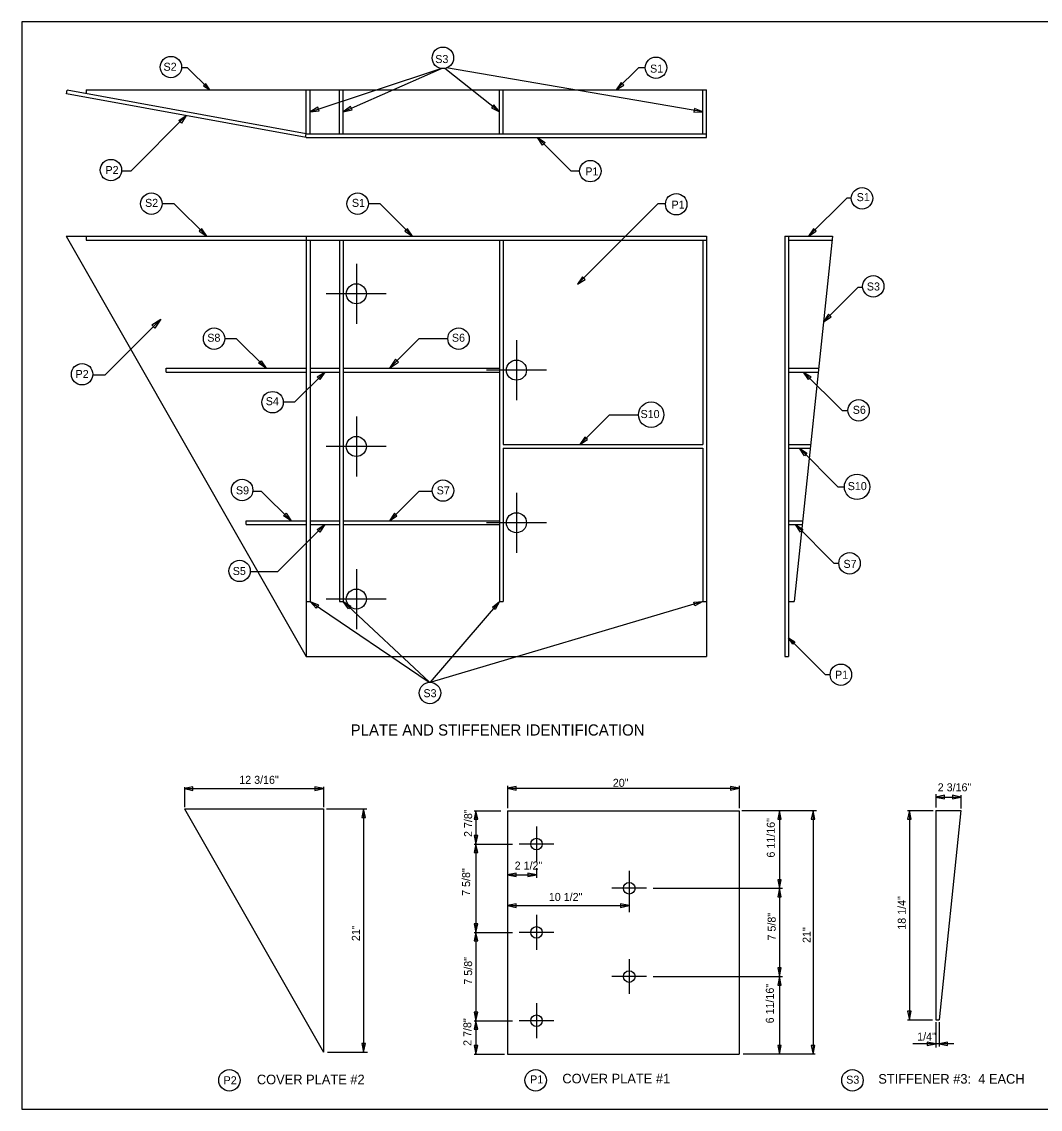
# Model space of a CAD drawing. Extents: x -439.1 to -407.9, y -458.1 to -437.7.
# Drawn here: x -439.11 to -420.02, y -458.05 to -437.68 of the extents above; entities that cross this region are included whole.
import ezdxf

# ---------------------------------------------------------------- set-up
doc = ezdxf.new("R2010")
doc.units = 0
for name, color, linetype in [('Common-Notes', 7, 'Continuous'), ('Draft_Named_Boundary', 7, 'Continuous'), ('Level 4', 7, 'Continuous'), ('Level 45', 7, 'Continuous')]:
    doc.layers.add(name, color=color, linetype=linetype)

msp = doc.modelspace()

# ---------------------------------------------------------------- linework, layer by layer
at = {"layer": 'Draft_Named_Boundary'}
msp.add_lwpolyline([(-439.109, -458.051), (-407.859, -458.051), (-407.859, -437.676), (-439.109, -437.676)], close=True, dxfattribs=at)
at = {"layer": 'Level 4'}
for p, q in [((-436.113, -438.531), (-436.008, -438.531)), ((-435.585, -438.954), (-436.008, -438.531)), ((-433.707, -439.364), (-431.256, -438.549)), ((-433.085, -439.364), (-431.246, -438.551)), ((-430.156, -439.364), (-431.179, -438.549)), ((-426.347, -439.364), (-431.147, -438.54)), ((-427.969, -438.954), (-427.546, -438.531)), ((-427.546, -438.531), (-427.425, -438.531)), ((-438.273, -439.025), (-438.26, -438.957)), ((-433.777, -439.844), (-438.273, -439.025)), ((-433.777, -439.774), (-438.26, -438.957)), ((-437.902, -438.954), (-426.277, -438.954)), ((-437.902, -438.954), (-437.902, -439.023)), ((-433.777, -439.774), (-433.777, -438.954)), ((-433.707, -439.774), (-433.707, -438.954)), ((-433.156, -439.774), (-433.156, -438.954)), ((-433.085, -439.774), (-433.085, -438.954)), ((-430.156, -439.774), (-430.156, -438.954)), ((-430.085, -439.774), (-430.085, -438.954)), ((-426.347, -439.774), (-426.347, -438.954)), ((-426.277, -439.844), (-426.277, -438.954)), ((-437.057, -440.467), (-436.025, -439.435)), ((-433.789, -439.842), (-433.777, -439.774)), ((-433.777, -439.774), (-426.277, -439.774)), ((-433.777, -439.844), (-426.277, -439.844)), ((-428.821, -440.467), (-429.443, -439.844)), ((-437.237, -440.467), (-437.057, -440.467)), ((-428.821, -440.467), (-428.655, -440.467)), ((-436.479, -441.082), (-436.256, -441.082)), ((-435.643, -441.695), (-436.256, -441.082)), ((-432.615, -441.082), (-432.4, -441.082)), ((-431.787, -441.695), (-432.4, -441.082)), ((-428.694, -442.595), (-427.18, -441.082)), ((-427.18, -441.082), (-427.046, -441.082)), ((-424.364, -441.695), (-423.644, -440.974)), ((-423.644, -440.974), (-423.564, -440.974)), ((-438.277, -441.695), (-433.777, -441.695)), ((-438.277, -441.695), (-433.777, -449.57)), ((-437.902, -441.695), (-437.902, -441.766)), ((-433.777, -441.695), (-426.277, -441.695)), ((-433.777, -441.695), (-433.777, -449.57)), ((-426.277, -441.695), (-426.277, -449.57)), ((-424.81, -441.695), (-424.81, -449.57)), ((-424.81, -441.695), (-423.919, -441.695)), ((-424.739, -441.695), (-424.739, -449.57)), ((-423.919, -441.695), (-424.632, -448.539)), ((-437.902, -441.766), (-433.777, -441.766)), ((-433.777, -441.766), (-426.277, -441.766)), ((-433.707, -441.766), (-433.707, -448.539)), ((-433.156, -441.766), (-433.156, -448.539)), ((-433.085, -441.766), (-433.085, -448.539)), ((-430.156, -441.766), (-430.156, -448.539)), ((-430.085, -441.766), (-430.085, -445.597)), ((-426.347, -441.766), (-426.347, -445.597)), ((-424.739, -441.766), (-423.919, -441.766)), ((-432.839, -442.211), (-432.839, -443.336)), ((-424.086, -443.296), (-423.438, -442.649)), ((-423.438, -442.649), (-423.352, -442.649)), ((-432.277, -442.773), (-433.402, -442.773)), ((-437.546, -444.288), (-436.502, -443.245)), ((-435.304, -443.609), (-435.091, -443.609)), ((-434.531, -444.168), (-435.091, -443.609)), ((-432.219, -444.168), (-431.66, -443.609)), ((-431.66, -443.609), (-431.119, -443.609)), ((-429.839, -443.641), (-429.839, -444.766)), ((-436.402, -444.238), (-436.402, -444.168)), ((-436.402, -444.168), (-433.777, -444.168)), ((-433.707, -444.168), (-433.156, -444.168)), ((-433.085, -444.168), (-430.156, -444.168)), ((-424.739, -444.168), (-424.177, -444.168)), ((-437.777, -444.288), (-437.546, -444.288)), ((-436.402, -444.238), (-433.777, -444.238)), ((-433.99, -444.798), (-433.431, -444.238)), ((-433.707, -444.238), (-433.156, -444.238)), ((-433.085, -444.238), (-430.156, -444.238)), ((-429.277, -444.203), (-430.402, -444.203)), ((-424.739, -444.238), (-424.177, -444.238)), ((-423.737, -444.959), (-424.458, -444.238)), ((-434.208, -444.798), (-433.99, -444.798)), ((-423.737, -444.959), (-423.628, -444.959)), ((-432.839, -445.07), (-432.839, -446.195)), ((-428.651, -445.597), (-428.092, -445.038)), ((-428.092, -445.038), (-427.551, -445.038)), ((-430.085, -445.597), (-426.347, -445.597)), ((-424.739, -445.597), (-424.326, -445.597)), ((-432.277, -445.633), (-433.402, -445.633)), ((-430.085, -445.668), (-426.347, -445.668)), ((-430.085, -445.668), (-430.085, -448.539)), ((-426.347, -445.668), (-426.347, -448.539)), ((-424.739, -445.668), (-424.333, -445.668)), ((-423.815, -446.389), (-424.536, -445.668)), ((-423.815, -446.389), (-423.692, -446.389)), ((-434.779, -446.468), (-434.62, -446.468)), ((-434.061, -447.027), (-434.62, -446.468)), ((-432.219, -447.027), (-431.66, -446.468)), ((-431.66, -446.468), (-431.415, -446.468)), ((-429.839, -446.5), (-429.839, -447.625)), ((-434.902, -447.097), (-434.902, -447.027)), ((-434.902, -447.027), (-433.777, -447.027)), ((-433.707, -447.027), (-433.156, -447.027)), ((-433.085, -447.027), (-430.156, -447.027)), ((-424.739, -447.027), (-424.474, -447.027)), ((-434.902, -447.097), (-433.777, -447.097)), ((-434.312, -447.978), (-433.431, -447.097)), ((-433.707, -447.097), (-433.156, -447.097)), ((-433.085, -447.097), (-430.156, -447.097)), ((-429.277, -447.062), (-430.402, -447.062)), ((-424.739, -447.097), (-424.482, -447.097)), ((-423.89, -447.818), (-424.611, -447.097)), ((-423.89, -447.818), (-423.798, -447.818)), ((-434.826, -447.978), (-434.312, -447.978)), ((-432.839, -447.929), (-432.839, -449.054)), ((-433.777, -448.539), (-433.707, -448.539)), ((-433.707, -448.539), (-431.474, -450.05)), ((-432.277, -448.492), (-433.402, -448.492)), ((-433.156, -448.539), (-433.085, -448.539)), ((-433.085, -448.539), (-431.471, -450.05)), ((-430.156, -448.539), (-431.454, -450.05)), ((-426.347, -448.539), (-431.436, -450.051)), ((-430.156, -448.539), (-430.085, -448.539)), ((-426.347, -448.539), (-426.277, -448.539)), ((-424.739, -448.539), (-424.632, -448.539)), ((-424.052, -449.905), (-424.739, -449.218)), ((-433.777, -449.57), (-426.277, -449.57)), ((-424.81, -449.57), (-424.739, -449.57)), ((-424.052, -449.905), (-423.96, -449.905)), ((-436.062, -452.014), (-436.062, -452.392)), ((-436.062, -452.044), (-433.457, -452.044)), ((-433.457, -452.012), (-433.457, -452.391)), ((-430.006, -451.991), (-430.006, -452.41)), ((-430.006, -452.037), (-425.664, -452.037)), ((-425.664, -451.991), (-425.664, -452.41)), ((-421.98, -452.146), (-421.98, -452.398)), ((-421.98, -452.201), (-421.51, -452.201)), ((-421.51, -452.164), (-421.51, -452.416)), ((-436.062, -452.423), (-433.457, -452.423)), ((-436.062, -452.423), (-433.457, -456.981)), ((-433.457, -452.423), (-433.457, -456.981)), ((-433.4, -452.423), (-432.645, -452.423)), ((-432.702, -452.423), (-432.702, -456.981)), ((-430.63, -452.458), (-430.132, -452.458)), ((-430.597, -452.458), (-430.597, -453.082)), ((-430.006, -452.458), (-425.664, -452.458)), ((-430.006, -452.458), (-430.006, -457.016)), ((-425.664, -452.458), (-425.664, -457.016)), ((-424.215, -452.458), (-425.618, -452.458)), ((-424.91, -452.458), (-424.91, -453.91)), ((-424.279, -452.458), (-424.279, -457.016)), ((-422.509, -452.453), (-422.03, -452.453)), ((-422.476, -452.453), (-422.476, -456.374)), ((-421.98, -452.453), (-421.98, -456.374)), ((-421.98, -452.453), (-421.51, -452.453)), ((-421.51, -452.453), (-421.918, -456.374)), ((-429.463, -452.756), (-429.463, -453.408)), ((-430.63, -453.082), (-429.914, -453.082)), ((-430.597, -453.082), (-430.597, -454.737)), ((-429.137, -453.082), (-429.788, -453.082)), ((-429.463, -453.534), (-429.463, -453.718)), ((-430.006, -453.66), (-429.463, -453.66)), ((-427.726, -453.584), (-427.726, -454.361)), ((-427.401, -453.91), (-428.052, -453.91)), ((-427.275, -453.91), (-424.855, -453.91)), ((-424.91, -453.91), (-424.91, -455.564)), ((-430.006, -454.235), (-427.726, -454.235)), ((-429.463, -454.411), (-429.463, -455.063)), ((-430.63, -454.737), (-429.914, -454.737)), ((-430.597, -454.737), (-430.597, -456.392)), ((-429.137, -454.737), (-429.788, -454.737)), ((-427.726, -455.239), (-427.726, -455.89)), ((-427.401, -455.564), (-428.052, -455.564)), ((-427.275, -455.564), (-424.855, -455.564)), ((-424.91, -455.564), (-424.91, -457.016)), ((-429.463, -456.066), (-429.463, -456.717)), ((-430.63, -456.392), (-429.914, -456.392)), ((-430.597, -456.392), (-430.597, -457.016)), ((-429.137, -456.392), (-429.788, -456.392)), ((-422.509, -456.374), (-422.041, -456.374)), ((-421.98, -456.374), (-421.918, -456.374)), ((-421.98, -456.417), (-421.98, -456.892)), ((-421.918, -456.417), (-421.918, -456.877)), ((-433.382, -456.981), (-432.627, -456.981)), ((-421.98, -456.825), (-422.413, -456.825)), ((-421.918, -456.825), (-421.98, -456.825)), ((-421.642, -456.825), (-421.918, -456.825)), ((-430.63, -457.016), (-430.064, -457.016)), ((-430.006, -457.016), (-425.664, -457.016)), ((-424.24, -457.016), (-425.587, -457.016))]:
    msp.add_line(p, q, dxfattribs=at)
for points in [[(-435.703, -438.876), (-435.585, -438.954), (-435.662, -438.836)], [(-427.876, -438.812), (-427.969, -438.954), (-427.827, -438.861)], [(-433.56, -439.279), (-433.707, -439.364), (-433.538, -439.344)], [(-432.947, -439.265), (-433.085, -439.364), (-432.92, -439.328)], [(-430.307, -439.287), (-430.156, -439.364), (-430.264, -439.234)], [(-436.167, -439.528), (-436.025, -439.435), (-436.118, -439.576)], [(-426.516, -439.37), (-426.347, -439.364), (-426.505, -439.302)], [(-429.35, -439.986), (-429.443, -439.844), (-429.301, -439.937)], [(-435.785, -441.602), (-435.643, -441.695), (-435.736, -441.553)], [(-431.929, -441.602), (-431.787, -441.695), (-431.88, -441.553)], [(-424.271, -441.553), (-424.364, -441.695), (-424.223, -441.602)], [(-428.601, -442.454), (-428.694, -442.595), (-428.552, -442.502)], [(-423.993, -443.154), (-424.086, -443.296), (-423.944, -443.203)], [(-436.672, -443.356), (-436.502, -443.245), (-436.614, -443.415)], [(-434.624, -444.026), (-434.531, -444.168), (-434.673, -444.075)], [(-432.108, -443.998), (-432.219, -444.168), (-432.049, -444.056)], [(-433.573, -444.331), (-433.431, -444.238), (-433.524, -444.38)], [(-424.365, -444.38), (-424.458, -444.238), (-424.316, -444.331)], [(-428.558, -445.456), (-428.651, -445.597), (-428.51, -445.504)], [(-424.443, -445.81), (-424.536, -445.668), (-424.394, -445.761)], [(-434.154, -446.885), (-434.061, -447.027), (-434.203, -446.934)], [(-432.126, -446.885), (-432.219, -447.027), (-432.077, -446.934)], [(-433.573, -447.19), (-433.431, -447.097), (-433.524, -447.239)], [(-424.518, -447.239), (-424.611, -447.097), (-424.469, -447.19)], [(-433.589, -448.66), (-433.707, -448.539), (-433.55, -448.603)], [(-432.988, -448.677), (-433.085, -448.539), (-432.941, -448.627)], [(-430.29, -448.642), (-430.156, -448.539), (-430.238, -448.687)], [(-426.516, -448.553), (-426.347, -448.539), (-426.496, -448.619)], [(-424.662, -449.336), (-424.739, -449.218), (-424.621, -449.295)], [(-435.901, -452.011), (-436.062, -452.044), (-435.901, -452.078)], [(-433.617, -452.078), (-433.457, -452.044), (-433.617, -452.011)], [(-429.845, -452.003), (-430.006, -452.037), (-429.845, -452.07)], [(-425.825, -452.07), (-425.664, -452.037), (-425.825, -452.003)], [(-421.82, -452.168), (-421.98, -452.201), (-421.82, -452.234)], [(-421.67, -452.234), (-421.51, -452.201), (-421.67, -452.168)], [(-432.669, -452.583), (-432.702, -452.423), (-432.735, -452.583)], [(-430.564, -452.618), (-430.597, -452.458), (-430.63, -452.618)], [(-424.876, -452.618), (-424.91, -452.458), (-424.943, -452.618)], [(-424.246, -452.618), (-424.279, -452.458), (-424.313, -452.618)], [(-422.442, -452.613), (-422.476, -452.453), (-422.509, -452.613)], [(-430.63, -452.922), (-430.597, -453.082), (-430.564, -452.922)], [(-430.564, -453.242), (-430.597, -453.082), (-430.63, -453.242)], [(-429.845, -453.626), (-430.006, -453.66), (-429.845, -453.693)], [(-429.623, -453.693), (-429.463, -453.66), (-429.623, -453.626)], [(-424.943, -453.75), (-424.91, -453.91), (-424.876, -453.75)], [(-424.876, -454.07), (-424.91, -453.91), (-424.943, -454.07)], [(-429.845, -454.202), (-430.006, -454.235), (-429.845, -454.268)], [(-427.887, -454.268), (-427.726, -454.235), (-427.887, -454.202)], [(-430.63, -454.577), (-430.597, -454.737), (-430.564, -454.577)], [(-430.564, -454.897), (-430.597, -454.737), (-430.63, -454.897)], [(-424.943, -455.404), (-424.91, -455.564), (-424.876, -455.404)], [(-424.876, -455.725), (-424.91, -455.564), (-424.943, -455.725)], [(-430.63, -456.232), (-430.597, -456.392), (-430.564, -456.232)], [(-430.564, -456.552), (-430.597, -456.392), (-430.63, -456.552)], [(-422.509, -456.213), (-422.476, -456.374), (-422.442, -456.213)], [(-422.141, -456.859), (-421.98, -456.825), (-422.141, -456.792)], [(-421.758, -456.792), (-421.918, -456.825), (-421.758, -456.859)], [(-432.735, -456.821), (-432.702, -456.981), (-432.669, -456.821)], [(-430.63, -456.856), (-430.597, -457.016), (-430.564, -456.856)], [(-424.943, -456.856), (-424.91, -457.016), (-424.876, -456.856)], [(-424.313, -456.856), (-424.279, -457.016), (-424.246, -456.856)]]:
    msp.add_lwpolyline(points, close=True, dxfattribs=at)
for centre, radius in [((-431.217, -438.352), 0.201), ((-436.314, -438.525), 0.201), ((-427.224, -438.538), 0.201), ((-437.438, -440.455), 0.201), ((-428.454, -440.475), 0.201), ((-436.68, -441.085), 0.201), ((-432.815, -441.085), 0.201), ((-426.845, -441.095), 0.201), ((-423.363, -440.984), 0.201), ((-423.152, -442.633), 0.201), ((-432.839, -442.773), 0.188), ((-435.505, -443.613), 0.201), ((-430.924, -443.613), 0.201), ((-437.978, -444.28), 0.201), ((-429.839, -444.203), 0.188), ((-434.409, -444.804), 0.201), ((-423.427, -444.957), 0.201), ((-427.314, -445.038), 0.238), ((-432.839, -445.633), 0.188), ((-423.455, -446.389), 0.238), ((-434.979, -446.449), 0.201), ((-431.215, -446.46), 0.201), ((-429.839, -447.062), 0.188), ((-423.597, -447.822), 0.201), ((-435.027, -447.965), 0.201), ((-432.839, -448.492), 0.188), ((-423.759, -449.91), 0.201), ((-431.459, -450.251), 0.201), ((-429.463, -453.082), 0.109), ((-427.726, -453.91), 0.109), ((-429.463, -454.737), 0.109), ((-427.726, -455.564), 0.109), ((-429.463, -456.392), 0.109), ((-435.217, -457.509), 0.201), ((-429.479, -457.509), 0.201), ((-423.542, -457.509), 0.201)]:
    msp.add_circle(centre, radius, dxfattribs=at)

# ---------------------------------------------------------------- texts
at = {"layer": 'Common-Notes'}
for s, height, p in [('PLATE AND STIFFENER IDENTIFICATION', 0.21, (-432.946, -451.05)), ('COVER PLATE #2', 0.18, (-434.703, -457.583)), ('COVER PLATE #1', 0.18, (-428.978, -457.566)), ('STIFFENER #3:  4 EACH', 0.18, (-423.058, -457.572))]:
    msp.add_text(s, height=height, dxfattribs=at).set_placement(p)
at = {"layer": 'Level 4'}
for s, p in [('S2', (-436.452, -438.594)), ('S3', (-431.36, -438.45)), ('S1', (-427.335, -438.629)), ('P2', (-437.54, -440.529)), ('P1', (-428.548, -440.554)), ('S1', (-423.463, -441.037)), ('S2', (-436.798, -441.144)), ('S1', (-432.922, -441.144)), ('P1', (-426.932, -441.178)), ('S3', (-423.272, -442.711)), ('S8', (-435.632, -443.671)), ('S6', (-431.048, -443.671)), ('P2', (-438.1, -444.351)), ('S4', (-434.536, -444.86)), ('S10', (-427.513, -445.101)), ('S6', (-423.536, -445.022)), ('S9', (-435.095, -446.53)), ('S7', (-431.333, -446.53)), ('S10', (-423.631, -446.451)), ('S7', (-423.71, -447.908)), ('S5', (-435.155, -448.041)), ('P1', (-423.869, -449.985)), ('S3', (-431.581, -450.331)), ('P1', (-429.582, -457.566)), ('P2', (-435.326, -457.583)), ('S3', (-423.659, -457.572))]:
    msp.add_text(s, height=0.15, dxfattribs=at).set_placement(p)
at = {"layer": 'Level 45'}
for s, p in [('12 3/16"', (-435.033, -451.954)), ('20"', (-428.033, -452.01)), ('2 3/16"', (-421.944, -452.094)), ('2 1/2"', (-429.872, -453.56)), ('10 1/2"', (-429.232, -454.148)), ('1/4"', (-422.329, -456.764))]:
    msp.add_text(s, height=0.15, dxfattribs=at).set_placement(p)
for s, p in [('2 7/8"', (-430.669, -452.95)), ('6 11/16"', (-424.997, -453.336)), ('7 5/8"', (-430.707, -454.053)), ('18 1/4"', (-422.543, -454.687)), ('7 5/8"', (-424.981, -454.889)), ('21"', (-432.773, -454.9)), ('21"', (-424.325, -454.935)), ('7 5/8"', (-430.669, -455.716)), ('6 11/16"', (-425.015, -456.442)), ('2 7/8"', (-430.683, -456.864))]:
    msp.add_text(s, height=0.15, rotation=90, dxfattribs=at).set_placement(p)

doc.saveas('drawing.dxf')
